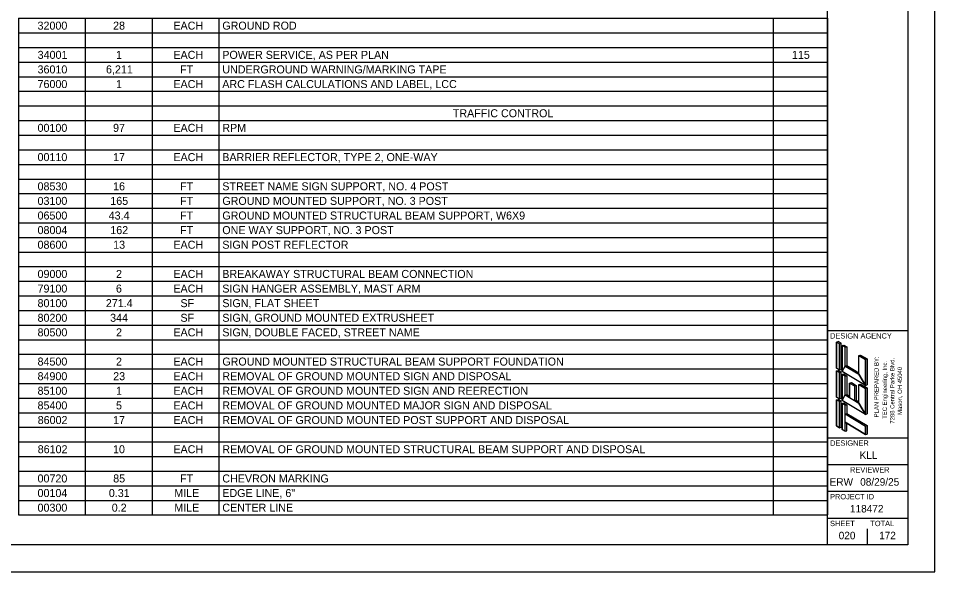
# Model space of a CAD drawing. Extents: x 0 to 34, y 0 to 22.
# Drawn here: x 16.92 to 34, y 0 to 10.33 of the extents above; entities that cross this region are included whole.
import ezdxf

# ---------------------------------------------------------------- set-up
doc = ezdxf.new("R2010")
doc.units = 0
for name, color, linetype in [('Default', 7, 'Continuous'), ('SH_Border', 7, 'Continuous'), ('SH_Cut_Line', 7, 'Continuous'), ('SH_Data', 7, 'Continuous'), ('SH_Text', 7, 'Continuous')]:
    doc.layers.add(name, color=color, linetype=linetype)

msp = doc.modelspace()

# ---------------------------------------------------------------- linework, layer by layer
at = {"layer": 'SH_Border'}
for p, q in [((32, 0.5), (32, 21.5)), ((32, 4.5), (33.5, 4.5)), ((32, 2.5), (33.5, 2.5)), ((32, 2), (33.5, 2)), ((32, 1.5), (33.5, 1.5)), ((32, 1), (33.5, 1))]:
    msp.add_line(p, q, dxfattribs=at)
msp.add_lwpolyline([(1.5, 21.5), (33.5, 21.5), (33.5, 0.5), (1.5, 0.5)], close=True, dxfattribs=at)
at = {"layer": 'SH_Cut_Line'}
msp.add_lwpolyline([(0, 0), (34, 0), (34, 22), (0, 22)], close=True, dxfattribs=at)
at = {"layer": 'SH_Data'}
for p, q in [((32.75, 3.5), (32.75, 3.5)), ((32.75, 0.5), (32.75, 0.8)), ((32.375, 0.675), (32.375, 0.675))]:
    msp.add_line(p, q, dxfattribs=at)
at = {"layer": 'SH_Text'}
for p, q in [((16.919, 10.325), (19.411, 10.325)), ((16.919, 10.325), (16.919, 10.053)), ((18.165, 10.325), (18.165, 10.053)), ((19.411, 10.325), (20.657, 10.325)), ((19.411, 10.325), (19.411, 10.053)), ((20.657, 10.325), (32, 10.325)), ((20.657, 10.325), (20.657, 10.053)), ((30.988, 10.325), (30.988, 10.053)), ((32, 10.325), (32, 10.053)), ((16.919, 10.053), (19.411, 10.053)), ((16.919, 10.053), (16.919, 9.235)), ((18.165, 10.053), (18.165, 9.235)), ((19.411, 10.053), (20.657, 10.053)), ((19.411, 10.053), (19.411, 9.235)), ((20.657, 10.053), (32, 10.053)), ((20.657, 10.053), (20.657, 9.235)), ((30.988, 10.053), (30.988, 9.235)), ((32, 10.053), (32, 9.235)), ((16.919, 9.78), (19.411, 9.78)), ((19.411, 9.78), (20.657, 9.78)), ((20.657, 9.78), (32, 9.78)), ((16.919, 9.508), (19.411, 9.508)), ((19.411, 9.508), (20.657, 9.508)), ((20.657, 9.508), (32, 9.508)), ((16.919, 9.235), (19.411, 9.235)), ((16.919, 9.235), (16.919, 8.69)), ((18.165, 9.235), (18.165, 8.69)), ((19.411, 9.235), (20.657, 9.235)), ((19.411, 9.235), (19.411, 8.69)), ((20.657, 9.235), (32, 9.235)), ((20.657, 9.235), (20.657, 8.69)), ((30.988, 9.235), (30.988, 8.69)), ((32, 9.235), (32, 8.69)), ((16.919, 8.963), (19.411, 8.963)), ((19.411, 8.963), (20.657, 8.963)), ((20.657, 8.963), (32, 8.963)), ((16.919, 8.69), (19.411, 8.69)), ((16.919, 8.69), (16.919, 7.872)), ((18.165, 8.69), (18.165, 7.872)), ((19.411, 8.69), (20.657, 8.69)), ((19.411, 8.69), (19.411, 7.872)), ((20.657, 8.69), (32, 8.69)), ((20.657, 8.69), (20.657, 7.872)), ((30.988, 8.69), (30.988, 7.872)), ((32, 8.69), (32, 7.872)), ((16.919, 8.417), (19.411, 8.417)), ((19.411, 8.417), (20.657, 8.417)), ((20.657, 8.417), (32, 8.417)), ((16.919, 8.145), (19.411, 8.145)), ((19.411, 8.145), (20.657, 8.145)), ((20.657, 8.145), (32, 8.145)), ((16.919, 7.872), (19.411, 7.872)), ((16.919, 7.872), (16.919, 7.327)), ((18.165, 7.872), (18.165, 7.327)), ((19.411, 7.872), (20.657, 7.872)), ((19.411, 7.872), (19.411, 7.327)), ((20.657, 7.872), (32, 7.872)), ((20.657, 7.872), (20.657, 7.327)), ((30.988, 7.872), (30.988, 7.327)), ((32, 7.872), (32, 7.327)), ((16.919, 7.6), (19.411, 7.6)), ((19.411, 7.6), (20.657, 7.6)), ((20.657, 7.6), (32, 7.6)), ((16.919, 7.327), (19.411, 7.327)), ((16.919, 7.327), (16.919, 6.51)), ((18.165, 7.327), (18.165, 6.51)), ((19.411, 7.327), (20.657, 7.327)), ((19.411, 7.327), (19.411, 6.51)), ((20.657, 7.327), (32, 7.327)), ((20.657, 7.327), (20.657, 6.51)), ((30.988, 7.327), (30.988, 6.51)), ((32, 7.327), (32, 6.51)), ((16.919, 7.055), (19.411, 7.055)), ((19.411, 7.055), (20.657, 7.055)), ((20.657, 7.055), (32, 7.055)), ((16.919, 6.782), (19.411, 6.782)), ((19.411, 6.782), (20.657, 6.782)), ((20.657, 6.782), (32, 6.782)), ((16.919, 6.51), (19.411, 6.51)), ((16.919, 6.51), (16.919, 5.419)), ((18.165, 6.51), (18.165, 5.419)), ((19.411, 6.51), (20.657, 6.51)), ((19.411, 6.51), (19.411, 5.419)), ((20.657, 6.51), (32, 6.51)), ((20.657, 6.51), (20.657, 5.419)), ((30.988, 6.51), (30.988, 5.419)), ((32, 6.51), (32, 5.419)), ((16.919, 6.237), (19.411, 6.237)), ((19.411, 6.237), (20.657, 6.237)), ((20.657, 6.237), (32, 6.237)), ((16.919, 5.964), (19.411, 5.964)), ((19.411, 5.964), (20.657, 5.964)), ((20.657, 5.964), (32, 5.964)), ((16.919, 5.692), (19.411, 5.692)), ((19.411, 5.692), (20.657, 5.692)), ((20.657, 5.692), (32, 5.692)), ((16.919, 5.419), (19.411, 5.419)), ((16.919, 5.419), (16.919, 5.147)), ((18.165, 5.419), (18.165, 5.147)), ((19.411, 5.419), (20.657, 5.419)), ((19.411, 5.419), (19.411, 5.147)), ((20.657, 5.419), (32, 5.419)), ((20.657, 5.419), (20.657, 5.147)), ((30.988, 5.419), (30.988, 5.147)), ((32, 5.419), (32, 5.147)), ((16.919, 5.147), (19.411, 5.147)), ((16.919, 5.147), (16.919, 4.057)), ((18.165, 5.147), (18.165, 4.057)), ((19.411, 5.147), (20.657, 5.147)), ((19.411, 5.147), (19.411, 4.057)), ((20.657, 5.147), (32, 5.147)), ((20.657, 5.147), (20.657, 4.057)), ((30.988, 5.147), (30.988, 4.057)), ((32, 5.147), (32, 4.057)), ((16.919, 4.874), (19.411, 4.874)), ((19.411, 4.874), (20.657, 4.874)), ((20.657, 4.874), (32, 4.874)), ((16.919, 4.602), (19.411, 4.602)), ((19.411, 4.602), (20.657, 4.602)), ((20.657, 4.602), (32, 4.602)), ((16.919, 4.329), (19.411, 4.329)), ((19.411, 4.329), (20.657, 4.329)), ((20.657, 4.329), (32, 4.329)), ((32.169, 4.285), (32.201, 4.294)), ((32.169, 3.799), (32.169, 4.285)), ((32.223, 4.253), (32.169, 4.285)), ((32.255, 4.261), (32.201, 4.294)), ((32.223, 4.253), (32.255, 4.261)), ((32.223, 3.767), (32.223, 4.253)), ((32.255, 3.775), (32.255, 4.261)), ((32.277, 4.221), (32.309, 4.229)), ((32.331, 4.188), (32.277, 4.221)), ((32.277, 3.735), (32.277, 4.221)), ((32.309, 4.229), (32.363, 4.196)), ((32.331, 4.188), (32.363, 4.196)), ((32.331, 3.837), (32.331, 4.188)), ((32.363, 4.196), (32.363, 3.845)), ((16.919, 4.057), (19.411, 4.057)), ((16.919, 4.057), (16.919, 3.784)), ((18.165, 4.057), (18.165, 3.784)), ((19.411, 4.057), (20.657, 4.057)), ((19.411, 4.057), (19.411, 3.784)), ((20.657, 4.057), (32, 4.057)), ((20.657, 4.057), (20.657, 3.784)), ((30.988, 4.057), (30.988, 3.784)), ((32, 4.057), (32, 3.784)), ((32.587, 4.034), (32.62, 4.042)), ((32.587, 3.683), (32.587, 4.034)), ((32.709, 3.961), (32.587, 4.034)), ((32.62, 4.042), (32.741, 3.97)), ((32.709, 3.961), (32.741, 3.97)), ((32.709, 3.475), (32.709, 3.961)), ((32.741, 3.97), (32.741, 3.484)), ((16.919, 3.784), (19.411, 3.784)), ((16.919, 3.784), (16.919, 2.694)), ((18.165, 3.784), (18.165, 2.694)), ((19.411, 3.784), (20.657, 3.784)), ((19.411, 3.784), (19.411, 2.694)), ((20.657, 3.784), (32, 3.784)), ((20.657, 3.784), (20.657, 2.694)), ((30.988, 3.784), (30.988, 2.694)), ((32, 3.784), (32, 2.694)), ((32.223, 3.767), (32.169, 3.799)), ((32.223, 3.767), (32.255, 3.775)), ((32.331, 3.837), (32.363, 3.845)), ((32.587, 3.683), (32.331, 3.837)), ((32.363, 3.845), (32.587, 3.711)), ((32.169, 3.745), (32.201, 3.754)), ((32.169, 3.259), (32.169, 3.745)), ((32.223, 3.713), (32.169, 3.745)), ((32.255, 3.722), (32.201, 3.754)), ((32.223, 3.713), (32.255, 3.722)), ((32.223, 3.227), (32.223, 3.713)), ((32.255, 3.236), (32.255, 3.722)), ((32.709, 3.475), (32.277, 3.735)), ((32.277, 3.681), (32.309, 3.689)), ((32.277, 3.195), (32.277, 3.681)), ((32.331, 3.648), (32.277, 3.681)), ((32.309, 3.689), (32.363, 3.656)), ((32.331, 3.648), (32.363, 3.656)), ((32.331, 3.297), (32.331, 3.648)), ((32.363, 3.656), (32.363, 3.305)), ((16.919, 3.511), (19.411, 3.511)), ((19.411, 3.511), (20.657, 3.511)), ((20.657, 3.511), (32, 3.511)), ((32.415, 3.519), (32.448, 3.527)), ((32.415, 3.519), (32.415, 3.247)), ((32.415, 3.519), (32.503, 3.466)), ((32.448, 3.527), (32.535, 3.474)), ((32.503, 3.466), (32.535, 3.474)), ((32.503, 3.466), (32.503, 3.194)), ((32.535, 3.474), (32.535, 3.202)), ((32.587, 3.494), (32.62, 3.502)), ((32.587, 3.143), (32.587, 3.494)), ((32.709, 3.421), (32.587, 3.494)), ((32.62, 3.502), (32.741, 3.43)), ((32.709, 3.475), (32.741, 3.484)), ((32.709, 3.421), (32.741, 3.43)), ((32.709, 2.935), (32.709, 3.421)), ((32.741, 3.43), (32.741, 2.944)), ((32.223, 3.227), (32.169, 3.259)), ((32.331, 3.297), (32.363, 3.305)), ((32.415, 3.247), (32.331, 3.297)), ((32.363, 3.305), (32.415, 3.274)), ((16.919, 3.239), (19.411, 3.239)), ((19.411, 3.239), (20.657, 3.239)), ((20.657, 3.239), (32, 3.239)), ((32.169, 3.205), (32.201, 3.215)), ((32.169, 2.719), (32.169, 3.205)), ((32.223, 3.173), (32.169, 3.205)), ((32.255, 3.181), (32.201, 3.215)), ((32.222, 3.173), (32.255, 3.181)), ((32.223, 3.227), (32.255, 3.236)), ((32.223, 2.687), (32.223, 3.173)), ((32.255, 2.695), (32.255, 3.181)), ((32.709, 2.935), (32.277, 3.195)), ((32.277, 3.141), (32.309, 3.151)), ((32.331, 3.108), (32.277, 3.141)), ((32.277, 2.655), (32.277, 3.141)), ((32.309, 3.151), (32.363, 3.116)), ((32.331, 3.108), (32.363, 3.116)), ((32.331, 2.944), (32.331, 3.108)), ((32.363, 3.116), (32.363, 2.952)), ((32.503, 3.194), (32.535, 3.202)), ((32.587, 3.143), (32.503, 3.194)), ((32.535, 3.202), (32.587, 3.171)), ((16.919, 2.966), (19.411, 2.966)), ((19.411, 2.966), (20.657, 2.966)), ((20.657, 2.966), (32, 2.966)), ((32.331, 2.944), (32.363, 2.952)), ((32.331, 2.944), (32.709, 2.717)), ((32.363, 2.952), (32.741, 2.725)), ((32.709, 2.935), (32.741, 2.944)), ((32.331, 2.787), (32.709, 2.56)), ((32.331, 2.622), (32.331, 2.787)), ((32.363, 2.63), (32.363, 2.767)), ((16.919, 2.694), (19.411, 2.694)), ((16.919, 2.694), (16.919, 2.421)), ((18.165, 2.694), (18.165, 2.421)), ((19.411, 2.694), (20.657, 2.694)), ((19.411, 2.694), (19.411, 2.421)), ((20.657, 2.694), (32, 2.694)), ((20.657, 2.694), (20.657, 2.421)), ((30.988, 2.694), (30.988, 2.421)), ((32, 2.694), (32, 2.421)), ((32.223, 2.687), (32.169, 2.719)), ((32.223, 2.687), (32.255, 2.695)), ((32.331, 2.622), (32.277, 2.655)), ((32.331, 2.622), (32.363, 2.63)), ((32.709, 2.717), (32.741, 2.725)), ((32.709, 2.56), (32.709, 2.717)), ((32.709, 2.56), (32.741, 2.568)), ((32.741, 2.725), (32.741, 2.568)), ((16.919, 2.421), (19.411, 2.421)), ((16.919, 2.421), (16.919, 1.331)), ((18.165, 2.421), (18.165, 1.331)), ((19.411, 2.421), (20.657, 2.421)), ((19.411, 2.421), (19.411, 1.331)), ((20.657, 2.421), (32, 2.421)), ((20.657, 2.421), (20.657, 1.331)), ((30.988, 2.421), (30.988, 1.331)), ((32, 2.421), (32, 1.331)), ((16.919, 2.149), (19.411, 2.149)), ((19.411, 2.149), (20.657, 2.149)), ((20.657, 2.149), (32, 2.149)), ((16.919, 1.876), (19.411, 1.876)), ((19.411, 1.876), (20.657, 1.876)), ((20.657, 1.876), (32, 1.876)), ((16.919, 1.604), (19.411, 1.604)), ((19.411, 1.604), (20.657, 1.604)), ((20.657, 1.604), (32, 1.604)), ((16.919, 1.331), (19.411, 1.331)), ((16.919, 1.331), (16.919, 1.059)), ((18.165, 1.331), (18.165, 1.059)), ((19.411, 1.331), (20.657, 1.331)), ((19.411, 1.331), (19.411, 1.059)), ((20.657, 1.331), (32, 1.331)), ((20.657, 1.331), (20.657, 1.059)), ((30.988, 1.331), (30.988, 1.059)), ((32, 1.331), (32, 1.059)), ((16.919, 1.059), (19.411, 1.059)), ((19.411, 1.059), (20.657, 1.059)), ((20.657, 1.059), (32, 1.059))]:
    msp.add_line(p, q, dxfattribs=at)
for points in [[(32.169, 3.799), (32.223, 3.767), (32.223, 4.253), (32.169, 4.285)], [(32.277, 3.735), (32.331, 3.837), (32.331, 4.188), (32.277, 4.221)], [(32.709, 3.475), (32.587, 3.683), (32.587, 4.034), (32.709, 3.961)], [(32.277, 3.735), (32.331, 3.837), (32.587, 3.683), (32.709, 3.475)], [(32.169, 3.259), (32.223, 3.227), (32.223, 3.713), (32.169, 3.745)], [(32.277, 3.195), (32.331, 3.297), (32.331, 3.648), (32.277, 3.681)], [(32.415, 3.247), (32.415, 3.519), (32.503, 3.466), (32.503, 3.194)], [(32.709, 2.935), (32.587, 3.143), (32.587, 3.494), (32.709, 3.421)], [(32.277, 3.195), (32.331, 3.297), (32.587, 3.143), (32.709, 2.935)], [(32.169, 2.719), (32.223, 2.687), (32.223, 3.173), (32.169, 3.205)], [(32.277, 2.655), (32.331, 2.622), (32.331, 3.108), (32.277, 3.141)], [(32.331, 2.787), (32.331, 2.944), (32.709, 2.717), (32.709, 2.56)]]:
    msp.add_lwpolyline(points, close=True, dxfattribs=at)

# ---------------------------------------------------------------- texts
at = {"layer": 'Default'}
for s, p in [('PLAN PREPARED BY:', (32.954, 2.88)), ('7288 Central Parke Blvd.', (33.25, 2.762)), ('TEC Engineering, Inc.', (33.11, 2.851)), ('Mason, OH 45040', (33.39, 2.925))]:
    msp.add_text(s, height=0.08, rotation=90, dxfattribs=at).set_placement(p)
at = {"layer": 'SH_Data'}
for s, height, p in [('DESIGN AGENCY', 0.1, (32.05, 4.35)), ('DESIGNER', 0.1, (32.05, 2.35)), ('KLL', 0.14, (32.601, 2.105)), ('REVIEWER', 0.1, (32.422, 1.85)), ('ERW', 0.14, (32.042, 1.605)), ('08/29/25', 0.14, (32.611, 1.605)), ('PROJECT ID', 0.1, (32.05, 1.35)), ('118472', 0.14, (32.421, 1.105)), ('SHEET', 0.1, (32.05, 0.85)), ('TOTAL', 0.1, (32.8, 0.85)), ('020', 0.14, (32.211, 0.605)), ('172', 0.14, (32.964, 0.605))]:
    msp.add_text(s, height=height, dxfattribs=at).set_placement(p)
at = {"layer": 'SH_Text'}
for s, height, p in [('32000', 0.1493, (17.277, 10.114)), ('28', 0.1493, (18.685, 10.114)), ('EACH', 0.1493, (19.809, 10.114)), ('GROUND ROD', 0.1493, (20.721, 10.114)), ('34001', 0.1493, (17.279, 9.569)), ('1', 0.149, (18.74, 9.569)), ('EACH', 0.1493, (19.809, 9.569)), ('POWER SERVICE, AS PER PLAN', 0.14926, (20.721, 9.569)), ('115', 0.1493, (31.339, 9.569)), ('36010', 0.1493, (17.277, 9.297)), ('6,211', 0.1493, (18.553, 9.297)), ('FT', 0.1493, (19.934, 9.297)), ('UNDERGROUND WARNING/MARKING TAPE', 0.14926, (20.721, 9.297)), ('76000', 0.1493, (17.277, 9.024)), ('1', 0.149, (18.74, 9.024)), ('EACH', 0.1493, (19.809, 9.024)), ('ARC FLASH CALCULATIONS AND LABEL, LCC', 0.14926, (20.721, 9.024)), ('TRAFFIC CONTROL', 0.14926, (25.018, 8.479)), ('00100', 0.1493, (17.277, 8.207)), ('97', 0.1493, (18.685, 8.207)), ('EACH', 0.1493, (19.809, 8.207)), ('RPM', 0.1493, (20.721, 8.207)), ('00110', 0.1493, (17.277, 7.661)), ('17', 0.1493, (18.685, 7.661)), ('EACH', 0.1493, (19.809, 7.661)), ('BARRIER REFLECTOR, TYPE 2, ONE-WAY', 0.14926, (20.721, 7.661)), ('08530', 0.1493, (17.277, 7.116)), ('16', 0.1493, (18.685, 7.116)), ('FT', 0.1493, (19.934, 7.116)), ('STREET NAME SIGN SUPPORT, NO. 4 POST', 0.14926, (20.721, 7.116)), ('03100', 0.1493, (17.277, 6.844)), ('165', 0.1493, (18.633, 6.844)), ('FT', 0.1493, (19.934, 6.844)), ('GROUND MOUNTED SUPPORT, NO. 3 POST', 0.14926, (20.721, 6.844)), ('06500', 0.1493, (17.277, 6.571)), ('43.4', 0.1493, (18.603, 6.571)), ('FT', 0.1493, (19.934, 6.571)), ('GROUND MOUNTED STRUCTURAL BEAM SUPPORT, W6X9', 0.14926, (20.721, 6.571)), ('08004', 0.1493, (17.277, 6.299)), ('162', 0.1493, (18.633, 6.299)), ('FT', 0.1493, (19.934, 6.299)), ('ONE WAY SUPPORT, NO. 3 POST', 0.14926, (20.721, 6.299)), ('08600', 0.1493, (17.277, 6.026)), ('13', 0.1493, (18.687, 6.026)), ('EACH', 0.1493, (19.809, 6.026)), ('SIGN POST REFLECTOR', 0.14926, (20.721, 6.026)), ('09000', 0.1493, (17.277, 5.481)), ('2', 0.149, (18.74, 5.481)), ('EACH', 0.1493, (19.809, 5.481)), ('BREAKAWAY STRUCTURAL BEAM CONNECTION', 0.14926, (20.721, 5.481)), ('79100', 0.1493, (17.277, 5.208)), ('6', 0.149, (18.738, 5.208)), ('EACH', 0.1493, (19.809, 5.208)), ('SIGN HANGER ASSEMBLY, MAST ARM', 0.14926, (20.721, 5.208)), ('80100', 0.1493, (17.277, 4.936)), ('271.4', 0.1493, (18.55, 4.936)), ('SF', 0.1493, (19.941, 4.936)), ('SIGN, FLAT SHEET', 0.14926, (20.721, 4.936)), ('80200', 0.1493, (17.277, 4.663)), ('344', 0.1493, (18.63, 4.663)), ('SF', 0.1493, (19.941, 4.663)), ('SIGN, GROUND MOUNTED EXTRUSHEET', 0.14926, (20.721, 4.663)), ('80500', 0.1493, (17.277, 4.391)), ('2', 0.149, (18.74, 4.391)), ('EACH', 0.1493, (19.809, 4.391)), ('SIGN, DOUBLE FACED, STREET NAME', 0.14926, (20.721, 4.391)), ('84500', 0.1493, (17.277, 3.846)), ('2', 0.149, (18.74, 3.846)), ('EACH', 0.1493, (19.809, 3.846)), ('GROUND MOUNTED STRUCTURAL BEAM SUPPORT FOUNDATION', 0.14926, (20.721, 3.846)), ('84900', 0.1493, (17.277, 3.573)), ('23', 0.1493, (18.687, 3.573)), ('EACH', 0.1493, (19.809, 3.573)), ('REMOVAL OF GROUND MOUNTED SIGN AND DISPOSAL', 0.14926, (20.721, 3.573)), ('85100', 0.1493, (17.277, 3.301)), ('1', 0.149, (18.74, 3.301)), ('EACH', 0.1493, (19.809, 3.301)), ('REMOVAL OF GROUND MOUNTED SIGN AND REERECTION', 0.14926, (20.721, 3.301)), ('85400', 0.1493, (17.277, 3.028)), ('5', 0.149, (18.74, 3.028)), ('EACH', 0.1493, (19.809, 3.028)), ('REMOVAL OF GROUND MOUNTED MAJOR SIGN AND DISPOSAL', 0.14926, (20.721, 3.028)), ('86002', 0.1493, (17.28, 2.755)), ('17', 0.1493, (18.685, 2.755)), ('EACH', 0.1493, (19.809, 2.755)), ('REMOVAL OF GROUND MOUNTED POST SUPPORT AND DISPOSAL', 0.14926, (20.721, 2.755)), ('86102', 0.1493, (17.28, 2.21)), ('10', 0.1493, (18.684, 2.21)), ('EACH', 0.1493, (19.809, 2.21)), ('REMOVAL OF GROUND MOUNTED STRUCTURAL BEAM SUPPORT AND DISPOSAL', 0.14926, (20.721, 2.21)), ('00720', 0.1493, (17.277, 1.665)), ('85', 0.1493, (18.687, 1.665)), ('FT', 0.1493, (19.934, 1.665)), ('CHEVRON MARKING', 0.14926, (20.721, 1.665)), ('00104', 0.1493, (17.277, 1.393)), ('0.31', 0.1493, (18.606, 1.393)), ('MILE', 0.1493, (19.826, 1.393)), ('EDGE LINE, 6"', 0.14926, (20.721, 1.393)), ('00300', 0.1493, (17.277, 1.12)), ('0.2', 0.1493, (18.66, 1.12)), ('MILE', 0.1493, (19.826, 1.12)), ('CENTER LINE', 0.14926, (20.721, 1.12))]:
    msp.add_text(s, height=height, dxfattribs=at).set_placement(p)

doc.saveas('drawing.dxf')
